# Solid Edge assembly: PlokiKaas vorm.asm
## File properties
Author: KULL
Template: Iso Metric Assembly.asm
Last saved by: KULL
Revision: 1
Application: Solid Edge
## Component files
Plokikaas_1.par
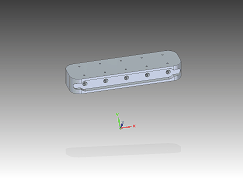
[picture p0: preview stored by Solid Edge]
